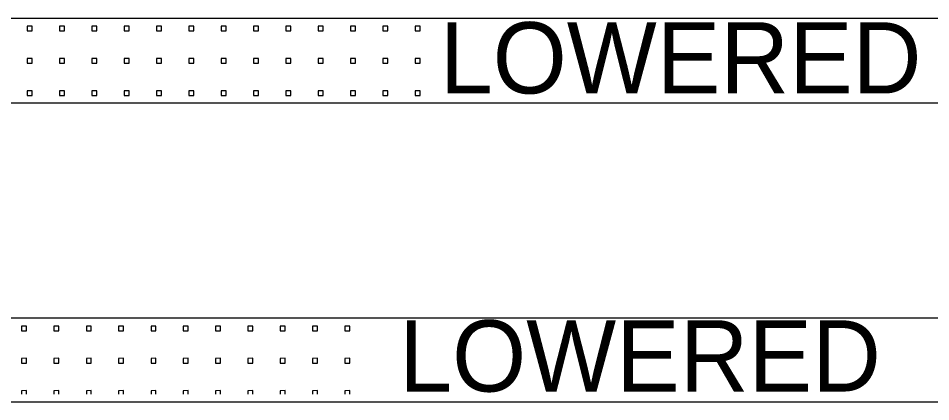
# Model space of a CAD drawing. Extents: x 10000 to 10825, y 10000 to 10530.
# Drawn here: x 10652.19 to 10697.01, y 10106.45 to 10125.29 of the extents above; entities that cross this region are included whole.
import ezdxf

# ---------------------------------------------------------------- set-up
doc = ezdxf.new("R2010")
doc.units = 0
doc.layers.add('Default', color=7, linetype='Continuous')
doc.layers.add('TextStructures', color=7, linetype='Continuous')

msp = doc.modelspace()

# ---------------------------------------------------------------- linework, layer by layer
at = {"layer": 'Default'}
for p, q in [((10490.187, 10125.289), (10784.11, 10125.289)), ((10490.187, 10121.141), (10784.11, 10121.141)), ((10490.187, 10110.58), (10784.11, 10110.58))]:
    msp.add_line(p, q, dxfattribs=at)
for points in [[(10652.878, 10124.666), (10652.878, 10124.905), (10652.639, 10124.904), (10652.639, 10124.666), (10652.878, 10124.666)], [(10652.878, 10124.666), (10652.878, 10124.905), (10652.639, 10124.904), (10652.639, 10124.666), (10652.878, 10124.666)], [(10654.464, 10124.666), (10654.464, 10124.905), (10654.225, 10124.904), (10654.225, 10124.666), (10654.464, 10124.666)], [(10654.464, 10124.666), (10654.464, 10124.905), (10654.225, 10124.904), (10654.225, 10124.666), (10654.464, 10124.666)], [(10656.054, 10124.666), (10656.054, 10124.905), (10655.815, 10124.904), (10655.815, 10124.666), (10656.054, 10124.666)], [(10656.054, 10124.666), (10656.054, 10124.905), (10655.815, 10124.904), (10655.815, 10124.666), (10656.054, 10124.666)], [(10657.64, 10124.666), (10657.64, 10124.905), (10657.401, 10124.904), (10657.401, 10124.666), (10657.64, 10124.666)], [(10657.64, 10124.666), (10657.64, 10124.905), (10657.401, 10124.904), (10657.401, 10124.666), (10657.64, 10124.666)], [(10659.23, 10124.666), (10659.23, 10124.905), (10658.991, 10124.904), (10658.991, 10124.666), (10659.23, 10124.666)], [(10659.23, 10124.666), (10659.23, 10124.905), (10658.991, 10124.904), (10658.991, 10124.666), (10659.23, 10124.666)], [(10660.817, 10124.666), (10660.817, 10124.905), (10660.578, 10124.904), (10660.578, 10124.666), (10660.817, 10124.666)], [(10660.817, 10124.666), (10660.817, 10124.905), (10660.578, 10124.904), (10660.578, 10124.666), (10660.817, 10124.666)], [(10662.406, 10124.666), (10662.406, 10124.905), (10662.167, 10124.904), (10662.167, 10124.666), (10662.406, 10124.666)], [(10662.406, 10124.666), (10662.406, 10124.905), (10662.167, 10124.904), (10662.167, 10124.666), (10662.406, 10124.666)], [(10663.993, 10124.666), (10663.993, 10124.905), (10663.754, 10124.904), (10663.754, 10124.666), (10663.993, 10124.666)], [(10663.993, 10124.666), (10663.993, 10124.905), (10663.754, 10124.904), (10663.754, 10124.666), (10663.993, 10124.666)], [(10665.582, 10124.666), (10665.582, 10124.905), (10665.344, 10124.904), (10665.344, 10124.666), (10665.582, 10124.666)], [(10665.582, 10124.666), (10665.582, 10124.905), (10665.344, 10124.904), (10665.344, 10124.666), (10665.582, 10124.666)], [(10667.169, 10124.666), (10667.169, 10124.905), (10666.93, 10124.904), (10666.93, 10124.666), (10667.169, 10124.666)], [(10667.169, 10124.666), (10667.169, 10124.905), (10666.93, 10124.904), (10666.93, 10124.666), (10667.169, 10124.666)], [(10668.759, 10124.666), (10668.759, 10124.905), (10668.52, 10124.904), (10668.52, 10124.666), (10668.759, 10124.666)], [(10668.759, 10124.666), (10668.759, 10124.905), (10668.52, 10124.904), (10668.52, 10124.666), (10668.759, 10124.666)], [(10670.345, 10124.666), (10670.345, 10124.905), (10670.106, 10124.904), (10670.106, 10124.666), (10670.345, 10124.666)], [(10670.345, 10124.666), (10670.345, 10124.905), (10670.106, 10124.904), (10670.106, 10124.666), (10670.345, 10124.666)], [(10671.935, 10124.666), (10671.935, 10124.905), (10671.696, 10124.904), (10671.696, 10124.666), (10671.935, 10124.666)], [(10671.935, 10124.666), (10671.935, 10124.905), (10671.696, 10124.904), (10671.696, 10124.666), (10671.935, 10124.666)], [(10652.878, 10123.078), (10652.878, 10123.317), (10652.639, 10123.316), (10652.639, 10123.078), (10652.878, 10123.078)], [(10652.878, 10123.078), (10652.878, 10123.317), (10652.639, 10123.316), (10652.639, 10123.078), (10652.878, 10123.078)], [(10654.464, 10123.078), (10654.464, 10123.317), (10654.225, 10123.316), (10654.225, 10123.078), (10654.464, 10123.078)], [(10654.464, 10123.078), (10654.464, 10123.317), (10654.225, 10123.316), (10654.225, 10123.078), (10654.464, 10123.078)], [(10656.054, 10123.078), (10656.054, 10123.317), (10655.815, 10123.316), (10655.815, 10123.078), (10656.054, 10123.078)], [(10656.054, 10123.078), (10656.054, 10123.317), (10655.815, 10123.316), (10655.815, 10123.078), (10656.054, 10123.078)], [(10657.64, 10123.078), (10657.64, 10123.317), (10657.401, 10123.316), (10657.401, 10123.078), (10657.64, 10123.078)], [(10657.64, 10123.078), (10657.64, 10123.317), (10657.401, 10123.316), (10657.401, 10123.078), (10657.64, 10123.078)], [(10659.23, 10123.078), (10659.23, 10123.317), (10658.991, 10123.316), (10658.991, 10123.078), (10659.23, 10123.078)], [(10659.23, 10123.078), (10659.23, 10123.317), (10658.991, 10123.316), (10658.991, 10123.078), (10659.23, 10123.078)], [(10660.817, 10123.078), (10660.817, 10123.317), (10660.578, 10123.316), (10660.578, 10123.078), (10660.817, 10123.078)], [(10660.817, 10123.078), (10660.817, 10123.317), (10660.578, 10123.316), (10660.578, 10123.078), (10660.817, 10123.078)], [(10662.406, 10123.078), (10662.406, 10123.317), (10662.167, 10123.316), (10662.167, 10123.078), (10662.406, 10123.078)], [(10662.406, 10123.078), (10662.406, 10123.317), (10662.167, 10123.316), (10662.167, 10123.078), (10662.406, 10123.078)], [(10663.993, 10123.078), (10663.993, 10123.317), (10663.754, 10123.316), (10663.754, 10123.078), (10663.993, 10123.078)], [(10663.993, 10123.078), (10663.993, 10123.317), (10663.754, 10123.316), (10663.754, 10123.078), (10663.993, 10123.078)], [(10665.582, 10123.078), (10665.582, 10123.317), (10665.344, 10123.316), (10665.344, 10123.078), (10665.582, 10123.078)], [(10665.582, 10123.078), (10665.582, 10123.317), (10665.344, 10123.316), (10665.344, 10123.078), (10665.582, 10123.078)], [(10667.169, 10123.078), (10667.169, 10123.317), (10666.93, 10123.316), (10666.93, 10123.078), (10667.169, 10123.078)], [(10667.169, 10123.078), (10667.169, 10123.317), (10666.93, 10123.316), (10666.93, 10123.078), (10667.169, 10123.078)], [(10668.759, 10123.078), (10668.759, 10123.317), (10668.52, 10123.316), (10668.52, 10123.078), (10668.759, 10123.078)], [(10668.759, 10123.078), (10668.759, 10123.317), (10668.52, 10123.316), (10668.52, 10123.078), (10668.759, 10123.078)], [(10670.345, 10123.078), (10670.345, 10123.317), (10670.106, 10123.316), (10670.106, 10123.078), (10670.345, 10123.078)], [(10670.345, 10123.078), (10670.345, 10123.317), (10670.106, 10123.316), (10670.106, 10123.078), (10670.345, 10123.078)], [(10671.935, 10123.078), (10671.935, 10123.317), (10671.696, 10123.316), (10671.696, 10123.078), (10671.935, 10123.078)], [(10671.935, 10123.078), (10671.935, 10123.317), (10671.696, 10123.316), (10671.696, 10123.078), (10671.935, 10123.078)], [(10652.878, 10121.49), (10652.878, 10121.729), (10652.639, 10121.728), (10652.639, 10121.49), (10652.878, 10121.49)], [(10652.878, 10121.49), (10652.878, 10121.729), (10652.639, 10121.728), (10652.639, 10121.49), (10652.878, 10121.49)], [(10654.464, 10121.49), (10654.464, 10121.729), (10654.225, 10121.728), (10654.225, 10121.49), (10654.464, 10121.49)], [(10654.464, 10121.49), (10654.464, 10121.729), (10654.225, 10121.728), (10654.225, 10121.49), (10654.464, 10121.49)], [(10656.054, 10121.49), (10656.054, 10121.729), (10655.815, 10121.728), (10655.815, 10121.49), (10656.054, 10121.49)], [(10656.054, 10121.49), (10656.054, 10121.729), (10655.815, 10121.728), (10655.815, 10121.49), (10656.054, 10121.49)], [(10657.64, 10121.49), (10657.64, 10121.729), (10657.401, 10121.728), (10657.401, 10121.49), (10657.64, 10121.49)], [(10657.64, 10121.49), (10657.64, 10121.729), (10657.401, 10121.728), (10657.401, 10121.49), (10657.64, 10121.49)], [(10659.23, 10121.49), (10659.23, 10121.729), (10658.991, 10121.728), (10658.991, 10121.49), (10659.23, 10121.49)], [(10659.23, 10121.49), (10659.23, 10121.729), (10658.991, 10121.728), (10658.991, 10121.49), (10659.23, 10121.49)], [(10660.817, 10121.49), (10660.817, 10121.729), (10660.578, 10121.728), (10660.578, 10121.49), (10660.817, 10121.49)], [(10660.817, 10121.49), (10660.817, 10121.729), (10660.578, 10121.728), (10660.578, 10121.49), (10660.817, 10121.49)], [(10662.406, 10121.49), (10662.406, 10121.729), (10662.167, 10121.728), (10662.167, 10121.49), (10662.406, 10121.49)], [(10662.406, 10121.49), (10662.406, 10121.729), (10662.167, 10121.728), (10662.167, 10121.49), (10662.406, 10121.49)], [(10663.993, 10121.49), (10663.993, 10121.729), (10663.754, 10121.728), (10663.754, 10121.49), (10663.993, 10121.49)], [(10663.993, 10121.49), (10663.993, 10121.729), (10663.754, 10121.728), (10663.754, 10121.49), (10663.993, 10121.49)], [(10665.582, 10121.49), (10665.582, 10121.729), (10665.344, 10121.728), (10665.344, 10121.49), (10665.582, 10121.49)], [(10665.582, 10121.49), (10665.582, 10121.729), (10665.344, 10121.728), (10665.344, 10121.49), (10665.582, 10121.49)], [(10667.169, 10121.49), (10667.169, 10121.729), (10666.93, 10121.728), (10666.93, 10121.49), (10667.169, 10121.49)], [(10667.169, 10121.49), (10667.169, 10121.729), (10666.93, 10121.728), (10666.93, 10121.49), (10667.169, 10121.49)], [(10668.759, 10121.49), (10668.759, 10121.729), (10668.52, 10121.728), (10668.52, 10121.49), (10668.759, 10121.49)], [(10668.759, 10121.49), (10668.759, 10121.729), (10668.52, 10121.728), (10668.52, 10121.49), (10668.759, 10121.49)], [(10670.345, 10121.49), (10670.345, 10121.729), (10670.106, 10121.728), (10670.106, 10121.49), (10670.345, 10121.49)], [(10670.345, 10121.49), (10670.345, 10121.729), (10670.106, 10121.728), (10670.106, 10121.49), (10670.345, 10121.49)], [(10671.935, 10121.49), (10671.935, 10121.729), (10671.696, 10121.728), (10671.696, 10121.49), (10671.935, 10121.49)], [(10671.935, 10121.49), (10671.935, 10121.729), (10671.696, 10121.728), (10671.696, 10121.49), (10671.935, 10121.49)], [(10652.598, 10109.933), (10652.598, 10110.173), (10652.361, 10110.171), (10652.361, 10109.933), (10652.598, 10109.933)], [(10652.598, 10109.933), (10652.598, 10110.173), (10652.361, 10110.171), (10652.361, 10109.933), (10652.598, 10109.933)], [(10654.186, 10109.933), (10654.186, 10110.173), (10653.949, 10110.171), (10653.949, 10109.933), (10654.186, 10109.933)], [(10654.186, 10109.933), (10654.186, 10110.173), (10653.949, 10110.171), (10653.949, 10109.933), (10654.186, 10109.933)], [(10655.774, 10109.933), (10655.774, 10110.173), (10655.538, 10110.171), (10655.538, 10109.933), (10655.774, 10109.933)], [(10655.774, 10109.933), (10655.774, 10110.173), (10655.538, 10110.171), (10655.538, 10109.933), (10655.774, 10109.933)], [(10657.362, 10109.933), (10657.362, 10110.173), (10657.125, 10110.171), (10657.125, 10109.933), (10657.362, 10109.933)], [(10657.362, 10109.933), (10657.362, 10110.173), (10657.125, 10110.171), (10657.125, 10109.933), (10657.362, 10109.933)], [(10658.95, 10109.933), (10658.95, 10110.173), (10658.714, 10110.171), (10658.714, 10109.933), (10658.95, 10109.933)], [(10658.95, 10109.933), (10658.95, 10110.173), (10658.714, 10110.171), (10658.714, 10109.933), (10658.95, 10109.933)], [(10660.538, 10109.933), (10660.538, 10110.173), (10660.301, 10110.171), (10660.301, 10109.933), (10660.538, 10109.933)], [(10660.538, 10109.933), (10660.538, 10110.173), (10660.301, 10110.171), (10660.301, 10109.933), (10660.538, 10109.933)], [(10662.127, 10109.933), (10662.127, 10110.173), (10661.89, 10110.171), (10661.89, 10109.933), (10662.127, 10109.933)], [(10662.127, 10109.933), (10662.127, 10110.173), (10661.89, 10110.171), (10661.89, 10109.933), (10662.127, 10109.933)], [(10663.714, 10109.933), (10663.714, 10110.173), (10663.477, 10110.171), (10663.477, 10109.933), (10663.714, 10109.933)], [(10663.714, 10109.933), (10663.714, 10110.173), (10663.477, 10110.171), (10663.477, 10109.933), (10663.714, 10109.933)], [(10665.303, 10109.933), (10665.303, 10110.173), (10665.066, 10110.171), (10665.066, 10109.933), (10665.303, 10109.933)], [(10665.303, 10109.933), (10665.303, 10110.173), (10665.066, 10110.171), (10665.066, 10109.933), (10665.303, 10109.933)], [(10666.89, 10109.933), (10666.89, 10110.173), (10666.654, 10110.171), (10666.654, 10109.933), (10666.89, 10109.933)], [(10666.89, 10109.933), (10666.89, 10110.173), (10666.654, 10110.171), (10666.654, 10109.933), (10666.89, 10109.933)], [(10668.479, 10109.933), (10668.479, 10110.173), (10668.242, 10110.171), (10668.242, 10109.933), (10668.479, 10109.933)], [(10668.479, 10109.933), (10668.479, 10110.173), (10668.242, 10110.171), (10668.242, 10109.933), (10668.479, 10109.933)], [(10652.598, 10108.346), (10652.598, 10108.585), (10652.361, 10108.584), (10652.361, 10108.346), (10652.598, 10108.346)], [(10652.598, 10108.346), (10652.598, 10108.585), (10652.361, 10108.584), (10652.361, 10108.346), (10652.598, 10108.346)], [(10654.186, 10108.346), (10654.186, 10108.585), (10653.949, 10108.584), (10653.949, 10108.346), (10654.186, 10108.346)], [(10654.186, 10108.346), (10654.186, 10108.585), (10653.949, 10108.584), (10653.949, 10108.346), (10654.186, 10108.346)], [(10655.774, 10108.346), (10655.774, 10108.585), (10655.538, 10108.584), (10655.538, 10108.346), (10655.774, 10108.346)], [(10655.774, 10108.346), (10655.774, 10108.585), (10655.538, 10108.584), (10655.538, 10108.346), (10655.774, 10108.346)], [(10657.362, 10108.346), (10657.362, 10108.585), (10657.125, 10108.584), (10657.125, 10108.346), (10657.362, 10108.346)], [(10657.362, 10108.346), (10657.362, 10108.585), (10657.125, 10108.584), (10657.125, 10108.346), (10657.362, 10108.346)], [(10658.95, 10108.346), (10658.95, 10108.585), (10658.714, 10108.584), (10658.714, 10108.346), (10658.95, 10108.346)], [(10658.95, 10108.346), (10658.95, 10108.585), (10658.714, 10108.584), (10658.714, 10108.346), (10658.95, 10108.346)], [(10660.538, 10108.346), (10660.538, 10108.585), (10660.301, 10108.584), (10660.301, 10108.346), (10660.538, 10108.346)], [(10660.538, 10108.346), (10660.538, 10108.585), (10660.301, 10108.584), (10660.301, 10108.346), (10660.538, 10108.346)], [(10662.127, 10108.346), (10662.127, 10108.585), (10661.89, 10108.584), (10661.89, 10108.346), (10662.127, 10108.346)], [(10662.127, 10108.346), (10662.127, 10108.585), (10661.89, 10108.584), (10661.89, 10108.346), (10662.127, 10108.346)], [(10663.714, 10108.346), (10663.714, 10108.585), (10663.477, 10108.584), (10663.477, 10108.346), (10663.714, 10108.346)], [(10663.714, 10108.346), (10663.714, 10108.585), (10663.477, 10108.584), (10663.477, 10108.346), (10663.714, 10108.346)], [(10665.303, 10108.346), (10665.303, 10108.585), (10665.066, 10108.584), (10665.066, 10108.346), (10665.303, 10108.346)], [(10665.303, 10108.346), (10665.303, 10108.585), (10665.066, 10108.584), (10665.066, 10108.346), (10665.303, 10108.346)], [(10666.89, 10108.346), (10666.89, 10108.585), (10666.654, 10108.584), (10666.654, 10108.346), (10666.89, 10108.346)], [(10666.89, 10108.346), (10666.89, 10108.585), (10666.654, 10108.584), (10666.654, 10108.346), (10666.89, 10108.346)], [(10668.479, 10108.346), (10668.479, 10108.585), (10668.242, 10108.584), (10668.242, 10108.346), (10668.479, 10108.346)], [(10668.479, 10108.346), (10668.479, 10108.585), (10668.242, 10108.584), (10668.242, 10108.346), (10668.479, 10108.346)], [(10652.598, 10106.997), (10652.361, 10106.995)], [(10652.361, 10106.995), (10652.361, 10106.832)], [(10652.598, 10106.832), (10652.598, 10106.997)], [(10654.186, 10106.997), (10653.949, 10106.995)], [(10653.949, 10106.995), (10653.949, 10106.832)], [(10654.186, 10106.832), (10654.186, 10106.997)], [(10655.774, 10106.997), (10655.538, 10106.995)], [(10655.538, 10106.995), (10655.538, 10106.832)], [(10655.774, 10106.832), (10655.774, 10106.997)], [(10657.362, 10106.997), (10657.125, 10106.995)], [(10657.125, 10106.995), (10657.125, 10106.832)], [(10657.362, 10106.832), (10657.362, 10106.997)], [(10658.95, 10106.997), (10658.714, 10106.995)], [(10658.714, 10106.995), (10658.714, 10106.832)], [(10658.95, 10106.832), (10658.95, 10106.997)], [(10660.538, 10106.997), (10660.301, 10106.995)], [(10660.301, 10106.995), (10660.301, 10106.832)], [(10660.538, 10106.832), (10660.538, 10106.997)], [(10662.127, 10106.997), (10661.89, 10106.995)], [(10661.89, 10106.995), (10661.89, 10106.832)], [(10662.127, 10106.832), (10662.127, 10106.997)], [(10663.714, 10106.997), (10663.477, 10106.995)], [(10663.477, 10106.995), (10663.477, 10106.832)], [(10663.714, 10106.832), (10663.714, 10106.997)], [(10665.303, 10106.997), (10665.066, 10106.995)], [(10665.066, 10106.995), (10665.066, 10106.832)], [(10665.303, 10106.832), (10665.303, 10106.997)], [(10666.89, 10106.997), (10666.654, 10106.995)], [(10666.654, 10106.995), (10666.654, 10106.832)], [(10666.89, 10106.832), (10666.89, 10106.997)], [(10668.479, 10106.997), (10668.242, 10106.995)], [(10668.242, 10106.995), (10668.242, 10106.832)], [(10668.479, 10106.832), (10668.479, 10106.997)]]:
    msp.add_lwpolyline(points, dxfattribs=at)
at = {"layer": 'TextStructures'}
msp.add_line((10490.187, 10106.453), (10784.11, 10106.453), dxfattribs=at)

# ---------------------------------------------------------------- texts
for p in [(10672.894, 10121.594), (10670.9, 10106.954)]:
    msp.add_text('LOWERED', height=3.5, rotation=0.0007, dxfattribs=at).set_placement(p)

doc.saveas('drawing.dxf')
